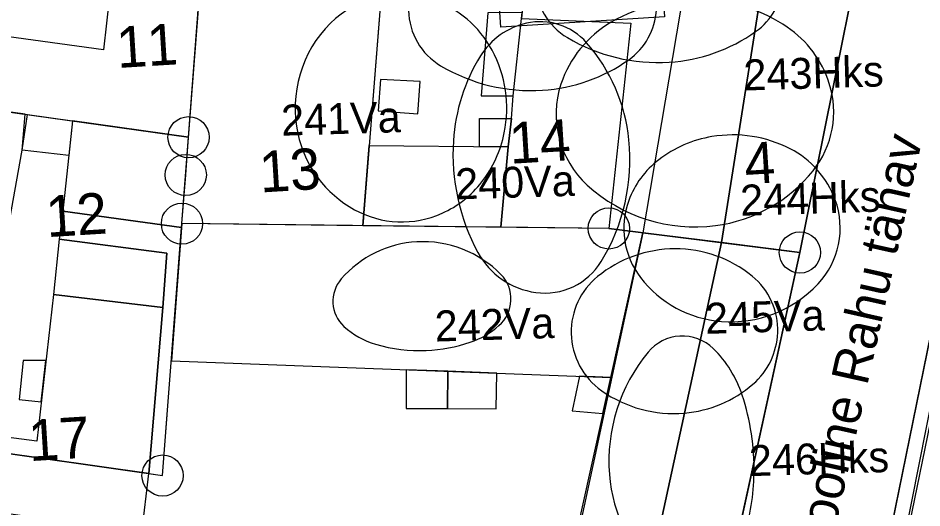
# Model space of a CAD drawing. Extents: x 738423 to 738903, y 6589762 to 6590172.
# Drawn here: x 738661.32 to 738705.18, y 6589904.84 to 6589928.62 of the extents above; entities that cross this region are included whole.
import ezdxf

# ---------------------------------------------------------------- set-up
doc = ezdxf.new("R2010")
doc.units = 0
for name, color, linetype in [('_1927_hoonestus', 7, 'Continuous'), ('_1927_katuse_kalded', 7, 'Continuous'), ('_1927_koordin_punktid_nr', 7, 'Continuous'), ('_1927_krundi_piir', 7, 'Continuous'), ('_1927_uhepoolne_katusekalle', 7, 'Continuous'), ('_ajalooline_kalmistu', 7, 'Continuous'), ('_arheol_Rüütli8_tranžee', 7, 'Continuous'), ('a_dendro_II_Vkl_puu', 7, 'Continuous'), ('a_dendro_III_vk_puu', 7, 'Continuous'), ('a_dendro_puu_nr', 7, 'Continuous'), ('a_dendro_V_vk_puu', 7, 'Continuous'), ('Default', 7, 'Continuous'), ('v_vormistus_tekst', 7, 'Continuous')]:
    doc.layers.add(name, color=color, linetype=linetype)

# ---------------------------------------------------------------- blocks, each defined once
blk = doc.blocks.new('_U690')
at = {"layer": 'Default'}
for centre, radius, start, end in [((-0.003374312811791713, 0.004949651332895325), 0.00931776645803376, 75.98881493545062, 141.81307745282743), ((-0.0037682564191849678, 0.003370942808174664), 0.010944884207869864, 34.56599987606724, 75.98881493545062), ((0.0014665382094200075, 0.0011420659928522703), 0.01547662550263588, 141.8130774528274, 191.68419382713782), ((-0.008227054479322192, 0.0002989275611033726), 0.016359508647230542, 0.9371401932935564, 34.56599987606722), ((-0.007523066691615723, 0.00031044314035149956), 0.01565542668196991, 330.06495980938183, 0.9371401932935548), ((0.0005393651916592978, 0.0009503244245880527), 0.014529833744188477, 191.6841938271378, 235.6485071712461), ((-0.0030046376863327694, -0.002291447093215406), 0.01044140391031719, 292.02320364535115, 330.06495980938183), ((-0.002510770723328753, -0.003512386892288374), 0.00912436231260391, 235.6485071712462, 292.02320364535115)]:
    blk.add_arc(centre, radius, start, end, dxfattribs=at)
blk = doc.blocks.new('_U686')
at = {"layer": 'Default'}
for centre, radius, start, end in [((-0.0003832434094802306, 0.0056645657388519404), 0.006358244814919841, 95.27822777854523, 153.5383418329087), ((-0.00039005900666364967, 0.00573834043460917), 0.006284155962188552, 38.521789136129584, 95.27822777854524), ((-0.0086367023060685, -0.0008264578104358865), 0.016824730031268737, 4.749066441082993, 38.5217891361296), ((0.009291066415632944, 0.000849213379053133), 0.017164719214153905, 153.53834183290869, 188.00637392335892), ((-0.008165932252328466, -0.0007873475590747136), 0.016352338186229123, 330.06495980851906, 4.7490664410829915), ((0.00846837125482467, 0.0007334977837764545), 0.016333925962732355, 188.00637392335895, 219.56435589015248), ((0.0007720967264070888, -0.005934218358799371), 0.006038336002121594, 271.3152895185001, 330.06495980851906), ((0.0007651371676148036, -0.005631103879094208), 0.006341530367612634, 219.56435589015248, 271.3152895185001)]:
    blk.add_arc(centre, radius, start, end, dxfattribs=at)
blk = doc.blocks.new('_U687')
at = {"layer": 'Default'}
for centre, radius, start, end in [((-0.00037116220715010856, -0.013056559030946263), 0.020067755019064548, 90.63222332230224, 122.78378534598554), ((-0.00039611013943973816, -0.010795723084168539), 0.017806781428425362, 62.49553610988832, 90.63222332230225), ((0.004559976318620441, -0.0012769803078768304), 0.007075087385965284, 17.12942078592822, 62.49553610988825), ((-0.007146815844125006, -0.0025362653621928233), 0.00755431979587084, 122.78378534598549, 176.44105376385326), ((0.00557950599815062, -0.0009627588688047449), 0.006008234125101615, 315.5978339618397, 17.129420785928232), ((-0.008276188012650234, -0.002466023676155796), 0.006422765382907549, 176.44105376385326, 242.8863827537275), ((-0.0021885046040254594, 0.006644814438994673), 0.016881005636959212, 280.06075412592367, 315.59783396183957), ((-0.0025546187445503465, 0.008708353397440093), 0.01897677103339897, 242.8863827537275, 280.0607541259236)]:
    blk.add_arc(centre, radius, start, end, dxfattribs=at)
blk = doc.blocks.new('_U688')
at = {"layer": 'Default'}
for centre, radius, start, end in [((0.002276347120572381, 0.001824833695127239), 0.011651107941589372, 49.162226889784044, 106.55395243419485), ((0.0021298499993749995, 0.002317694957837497), 0.011136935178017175, 106.55395243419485, 155.37187784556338), ((0.0035985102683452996, 0.0033545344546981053), 0.009629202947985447, 345.3983052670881, 49.162226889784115), ((0.0006497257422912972, 0.002996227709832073), 0.009508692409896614, 155.37187784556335, 208.50422751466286), ((0.0028839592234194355, 0.00354068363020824), 0.010367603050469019, 302.57956319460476, 345.3983052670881), ((0.001212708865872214, 0.003301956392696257), 0.010149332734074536, 208.50422751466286, 236.55502715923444), ((0.001969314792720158, 0.0044474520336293), 0.011522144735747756, 236.5550271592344, 262.8497923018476), ((0.0020243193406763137, 0.0048859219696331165), 0.011964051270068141, 262.84979230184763, 302.5795631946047)]:
    blk.add_arc(centre, radius, start, end, dxfattribs=at)
blk = doc.blocks.new('_U691')
at = {"layer": 'Default'}
for centre, radius, start, end in [((-0.0028083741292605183, 0.00047341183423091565), 0.007831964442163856, 74.13779803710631, 131.76985430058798), ((-0.0030874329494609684, -0.0005086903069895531), 0.008852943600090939, 41.8695218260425, 74.13779803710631), ((-0.0007038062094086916, -0.0018829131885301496), 0.010991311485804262, 131.76985430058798, 179.78668610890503), ((-0.005143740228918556, -0.002351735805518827), 0.011614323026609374, 13.787819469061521, 41.8695218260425), ((-0.0057176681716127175, -0.0024925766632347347), 0.012205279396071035, 337.128887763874, 13.787819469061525), ((-0.00010478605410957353, -0.001885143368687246), 0.0115903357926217, 179.78668610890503, 231.21741391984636), ((-0.002818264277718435, -0.003715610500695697), 0.009058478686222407, 294.30882533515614, 337.12888776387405), ((-0.0023710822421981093, -0.0047056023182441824), 0.007972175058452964, 231.21741391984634, 294.30882533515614)]:
    blk.add_arc(centre, radius, start, end, dxfattribs=at)
blk = doc.blocks.new('_U692')
at = {"layer": 'Default'}
for centre, radius, start, end in [((-0.00015497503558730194, 0.0030520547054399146), 0.006980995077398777, 95.44933313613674, 149.1729911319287), ((-0.00015882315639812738, 0.003092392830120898), 0.006940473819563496, 43.483089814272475, 95.44933313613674), ((-0.0038243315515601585, -0.0003839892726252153), 0.011992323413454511, 4.545899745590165, 43.483089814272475), ((0.00427195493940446, 0.0004102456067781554), 0.01213627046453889, 149.17299113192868, 189.2546640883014), ((-0.00356945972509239, -0.0003637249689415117), 0.011736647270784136, 325.04588222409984, 4.545899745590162), ((0.003856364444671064, 0.0003425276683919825), 0.011715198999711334, 189.25466408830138, 225.10763018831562), ((0.0004963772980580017, -0.003205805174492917), 0.006775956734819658, 272.233731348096, 325.04588222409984), ((0.0004897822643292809, -0.0030367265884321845), 0.00694516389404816, 225.10763018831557, 272.23373134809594)]:
    blk.add_arc(centre, radius, start, end, dxfattribs=at)
blk = doc.blocks.new('_U689')
at = {"layer": 'Default'}
for centre, radius, start, end in [((0.002010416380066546, 0.004952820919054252), 0.003317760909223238, 53.54712692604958, 141.6807483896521), ((-0.0022180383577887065, -0.0007714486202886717), 0.010434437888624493, 7.36696495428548, 53.54712692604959), ((0.005484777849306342, 0.002207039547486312), 0.007746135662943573, 141.6807483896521, 168.01659018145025), ((0.012853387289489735, 0.000643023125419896), 0.015278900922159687, 168.01659018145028, 186.68626766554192), ((-0.0024000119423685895, -0.0007949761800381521), 0.010617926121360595, 318.66315816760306, 7.3669649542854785), ((0.012653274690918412, 0.0006195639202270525), 0.015077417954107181, 186.6862676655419, 203.18240556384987), ((0.006504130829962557, -0.002013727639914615), 0.008388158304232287, 203.18240556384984, 225.3605967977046), ((0.0030090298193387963, -0.005553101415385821), 0.003413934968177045, 225.36059679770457, 318.6631581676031)]:
    blk.add_arc(centre, radius, start, end, dxfattribs=at)
blk = doc.blocks.new('_U693')
at = {"layer": 'Default'}
for centre, radius, start, end in [((0.0014736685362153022, -0.0048970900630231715), 0.015073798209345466, 98.7443079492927, 142.7779679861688), ((0.0017097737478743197, -0.006432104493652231), 0.01662686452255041, 54.774629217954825, 98.74430794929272), ((0.008815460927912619, 0.003631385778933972), 0.004307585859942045, 320.0766918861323, 54.77462921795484), ((-0.0071794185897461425, 0.0016762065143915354), 0.004207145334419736, 142.77796798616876, 233.18140194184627), ((0.0036181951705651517, 0.007980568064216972), 0.01108452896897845, 292.371461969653, 320.0766918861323), ((-0.0035391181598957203, 0.006539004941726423), 0.010281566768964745, 233.18140194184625, 257.0506083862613), ((-0.001092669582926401, 0.019426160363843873), 0.023461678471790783, 273.4270301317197, 292.37146196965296), ((-0.0009858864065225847, 0.01764300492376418), 0.021675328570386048, 257.0506083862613, 273.4270301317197)]:
    blk.add_arc(centre, radius, start, end, dxfattribs=at)

msp = doc.modelspace()

# ---------------------------------------------------------------- linework, layer by layer
at = {"layer": '_1927_hoonestus'}
for points in [[(738670.9087498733, 6589940.043011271), (738679.7282311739, 6589939.8095354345), (738678.0506429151, 6589918.541122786), (738669.2749026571, 6589918.640213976), (738669.5947892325, 6589922.838186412)], [(738703.6658553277, 6589939.175840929), (738686.7916245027, 6589939.622548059), (738685.7524954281, 6589928.595336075), (738691.0609477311, 6589928.3767996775), (738689.9894215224, 6589918.406316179), (738699.2597677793, 6589917.239834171)], [(738665.758297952, 6589929.692470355), (738665.459647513, 6589927.08831797), (738656.5091354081, 6589928.314041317), (738656.3355450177, 6589927.0464446), (738654.8545915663, 6589927.249253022), (738654.4566176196, 6589924.9626378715), (738669.5947892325, 6589922.838186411), (738670.0996549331, 6589929.448830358)], [(738709.5552440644, 6589929.3606177), (738708.8892047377, 6589929.394066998), (738701.8048329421, 6589894.603709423), (738702.5737267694, 6589894.447139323), (738706.4549361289, 6589914.049006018)], [(738683.7945797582, 6589924.85083232), (738685.3485059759, 6589924.85083232), (738685.7524954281, 6589928.595336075), (738685.7811858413, 6589928.899798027), (738684.1245318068, 6589928.878209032)], [(738685.7524954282, 6589928.595336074), (738691.0609477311, 6589928.3767996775), (738689.9894215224, 6589918.406316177), (738684.7532568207, 6589918.465440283), (738685.1051996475, 6589922.369220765), (738685.2636060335, 6589923.746136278), (738685.3485059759, 6589924.85083232)], [(738678.9012558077, 6589925.63364723), (738678.7932013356, 6589924.111793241), (738680.7159516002, 6589923.975274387), (738680.827683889, 6589925.548927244)], [(738661.5130182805, 6589922.201342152), (738661.6687240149, 6589923.9505097), (738656.0626882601, 6589924.737246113), (738655.2835310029, 6589919.185217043), (738660.8355600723, 6589918.406059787)], [(738663.9585047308, 6589923.629167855), (738663.7786931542, 6589921.957619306), (738661.5130182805, 6589922.201342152), (738661.7796479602, 6589923.934942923)], [(738663.4879510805, 6589919.2548484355), (738669.2606745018, 6589918.45547633), (738669.2749026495, 6589918.640213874), (738669.5947891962, 6589922.838185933), (738663.9585047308, 6589923.629167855)], [(738683.7098079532, 6589922.382241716), (738683.7098079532, 6589923.746136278), (738685.2636060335, 6589923.746136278), (738685.1051996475, 6589922.369220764)], [(738678.3575582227, 6589922.43218567), (738685.1051996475, 6589922.369220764), (738684.7532568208, 6589918.465440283), (738678.0506429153, 6589918.541122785)], [(738663.4879510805, 6589919.2548484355), (738663.3130057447, 6589917.884922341), (738668.5407840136, 6589917.205109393), (738668.3392788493, 6589914.563788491), (738667.6613666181, 6589906.503844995), (738668.3328065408, 6589906.408085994), (738669.2606745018, 6589918.45547633)], [(738691.6412212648, 6589918.198471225), (738689.9894215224, 6589918.406316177), (738678.0506429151, 6589918.541122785), (738669.2749026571, 6589918.640213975), (738668.7620235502, 6589911.98101778), (738690.0879717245, 6589911.173226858)], [(738663.3130057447, 6589917.884922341), (738663.0394642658, 6589915.202400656), (738668.3392788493, 6589914.563788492), (738668.5407840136, 6589917.205109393)], [(738699.2597677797, 6589917.239834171), (738691.6412212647, 6589918.198471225), (738686.7271328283, 6589895.972376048), (738694.440862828, 6589895.179011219)], [(738662.2307096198, 6589908.078251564), (738653.9028397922, 6589909.158261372), (738653.8060863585, 6589908.479848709), (738667.6613666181, 6589906.503844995), (738668.3392788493, 6589914.563788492), (738663.0394642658, 6589915.202400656)], [(738662.6751140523, 6589911.992916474), (738661.5685084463, 6589911.992916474), (738661.3773991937, 6589910.101973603), (738662.4469901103, 6589909.9834207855)], [(738680.1532840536, 6589911.549536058), (738680.1532840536, 6589909.667903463), (738682.1639614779, 6589909.667903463), (738682.1842358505, 6589911.472607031)], [(738682.1842358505, 6589911.472607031), (738682.1639614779, 6589909.667903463), (738684.521090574, 6589909.641423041), (738684.5512583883, 6589911.382948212)], [(738688.5655816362, 6589911.230892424), (738688.2047210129, 6589909.544301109), (738689.7020185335, 6589909.427586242), (738690.0879717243, 6589911.173226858)], [(738655.3410315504, 6589908.260938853), (738655.0571223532, 6589905.406639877), (738667.3213049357, 6589903.626637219), (738667.6613666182, 6589906.503844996)]]:
    msp.add_lwpolyline(points, close=True, dxfattribs=at)
at = {"layer": '_1927_katuse_kalded'}
for points in [[(738703.6658553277, 6589939.175840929), (738697.9292015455, 6589933.403840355), (738695.4504945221, 6589917.7191527), (738699.2597677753, 6589917.239834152)], [(738693.6272828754, 6589929.981278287), (738691.6412212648, 6589918.198471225), (738695.4504945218, 6589917.719152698), (738697.9292015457, 6589933.403840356)], [(738695.4504945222, 6589917.719152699), (738691.6412212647, 6589918.198471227), (738685.1578836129, 6589887.989329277), (738688.93612634, 6589887.632248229)], [(738688.9361263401, 6589887.632248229), (738692.7143690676, 6589887.275167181), (738699.2597677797, 6589917.239834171), (738695.4504945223, 6589917.719152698)]]:
    msp.add_lwpolyline(points, close=True, dxfattribs=at)
at = {"layer": '_1927_koordin_punktid_nr'}
for centre in [(738669.5947892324, 6589922.838186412), (738669.45830989, 6589921.006172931), (738669.274902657, 6589918.640213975), (738689.9894215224, 6589918.406316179), (738699.2597677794, 6589917.23983417), (738668.3328065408, 6589906.408085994)]:
    msp.add_circle(centre, 0.9999999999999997, dxfattribs=at)
at = {"layer": '_1927_krundi_piir'}
for points in [[(738642.9591139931, 6589940.778512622), (738641.2530402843, 6589926.815593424), (738669.5947892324, 6589922.838186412)], [(738642.9591139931, 6589940.778512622), (738670.908755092, 6589940.043011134), (738703.6658553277, 6589939.175840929), (738699.2597677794, 6589917.23983417), (738689.9894215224, 6589918.406316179), (738669.274902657, 6589918.640213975), (738669.45830989, 6589921.006172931), (738669.5947892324, 6589922.838186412), (738670.908755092, 6589940.043011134)], [(738729.7703727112, 6589938.08823291), (738710.8186909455, 6589938.869503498), (738701.0341576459, 6589890.819030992), (738730.2687956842, 6589887.788909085)], [(738641.2530402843, 6589926.815593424), (738639.279366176, 6589910.5516114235), (738668.3328065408, 6589906.408085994), (738669.274902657, 6589918.640213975)], [(738699.2597677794, 6589917.23983417), (738686.9079452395, 6589860.693508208), (738653.160733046, 6589865.556898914), (738635.0048101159, 6589867.503013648), (738638.1290908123, 6589898.927727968), (738639.279366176, 6589910.5516114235)]]:
    msp.add_lwpolyline(points, dxfattribs=at)
at = {"layer": '_1927_uhepoolne_katusekalle'}
msp.add_lwpolyline([(738670.1667035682, 6589930.326732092), (738678.9700315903, 6589930.197104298), (738678.0506429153, 6589918.541122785), (738669.2749026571, 6589918.640213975)], close=True, dxfattribs=at)
at = {"layer": '_ajalooline_kalmistu'}
msp.add_lwpolyline([(738700.480405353, 6589884.053901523), (738711.8557000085, 6589939.5353000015), (738713.3969999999, 6589939.458000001), (738744.2612679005, 6589937.910991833), (738742.6678676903, 6589879.490577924)], close=True, dxfattribs=at)
at = {"layer": '_arheol_Rüütli8_tranžee'}
msp.add_lwpolyline([(738684.6874199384, 6589929.1563526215), (738692.6296929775, 6589929.666277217), (738692.6925779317, 6589928.686819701), (738684.7503048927, 6589928.176895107)], close=True, dxfattribs=at)

# ---------------------------------------------------------------- block references
at = {"layer": 'a_dendro_II_Vkl_puu', "xscale": 500.0000000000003, "yscale": 500.0000000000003, "rotation": 85.69234851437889}
msp.add_blockref('_U686', (738686.292, 6589929.021000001), dxfattribs=at)
at = {"layer": 'a_dendro_III_vk_puu', "xscale": 500.0000000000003, "yscale": 500.0000000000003, "rotation": 85.69234851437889}
for name, p in [('_U686', (738692.4450000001, 6589930.383000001)), ('_U688', (738681.4149999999, 6589923.042999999)), ('_U690', (738694.6830000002, 6589925.447)), ('_U687', (738685.9634679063, 6589922.699999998)), ('_U691', (738694.9720000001, 6589919.792999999)), ('_U689', (738680.654, 6589913.683000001)), ('_U692', (738693.18, 6589913.343000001))]:
    msp.add_blockref(name, p, dxfattribs=at)
at = {"layer": 'a_dendro_V_vk_puu', "xscale": 500.0000000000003, "yscale": 500.0000000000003, "rotation": 85.69234851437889}
msp.add_blockref('_U693', (738695.034, 6589906.495999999), dxfattribs=at)

# ---------------------------------------------------------------- texts
at = {"layer": '_1927_koordin_punktid_nr'}
for s, p in [('11', (738666.1531865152, 6589926.1975360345)), ('14', (738685.2103931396, 6589921.545361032)), ('13', (738673.0866834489, 6589920.150957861)), ('4', (738696.6257013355, 6589920.551177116)), ('12', (738662.7315087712, 6589917.983582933)), ('17', (738661.8836672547, 6589907.105503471))]:
    msp.add_text(s, height=1.9999999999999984, rotation=3.560863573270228, dxfattribs=at).set_placement(p)
at = {"layer": 'a_dendro_puu_nr'}
for s, p in [('243Hks', (738696.5452567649, 6589925.10499017)), ('241Va', (738674.1105096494, 6589922.909625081)), ('240Va', (738682.5575288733, 6589919.818900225)), ('244Hks', (738696.3877092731, 6589919.023103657)), ('245Va', (738694.6814037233, 6589913.286746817)), ('242Va', (738681.5619099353, 6589912.913103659)), ('246Hks', (738696.8112109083, 6589906.37729154))]:
    msp.add_text(s, height=1.5, rotation=1.7381147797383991, dxfattribs=at).set_placement(p)
at = {"layer": 'v_vormistus_tekst'}
msp.add_text('ajalooline Rahu tänav', height=1.7999999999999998, rotation=77.38923434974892, dxfattribs=at).set_placement((738700.1540242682, 6589900.152723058))

doc.saveas('drawing.dxf')
